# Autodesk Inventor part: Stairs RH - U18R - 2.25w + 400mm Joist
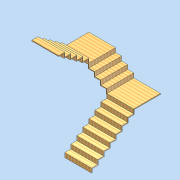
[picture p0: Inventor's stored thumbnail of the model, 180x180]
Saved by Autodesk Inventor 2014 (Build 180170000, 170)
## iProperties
Created: 2012-06
Part Number: Stairs RH - U18R - 2.25w + 400mm Joist
Document SubType Name: Modeling
Designer: david.appleford
Mass: 308572 g
Surface Area: 205460 cm^2
Volume: 308572 cm^3
Density: 1 g/cm^3
Cost Center: £1500.00
Description: Stairs RH - U18R - 2.25w + 400mm Joist
Material: Generic
Appearance: Wood (Pine)
Justset: False
Author: david.appleford
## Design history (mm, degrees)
sketch "Sketch1"
  geometry: L1 (0, 0)-(2970, 0); L2 (2970, 0)-(2970, 2360); L3 (2970, 2360)-(0, 2360); L4 (0, 2360)-(0, 0)
  constraints: 8 end point, 2 parallel, 1 horizontal, 1 perpendicular
  dimensions: "d0" = 2360 distance between parallel lines of L1 L3; "d1" = 2970 distance between parallel lines of L2 L4
extrude "Extrusion1" new body sketch "Sketch1" distance "d2" = 3213; taper "d3" = 0 deg
sketch "Sketch2" dims "d10" = 10, "d20" = 10
  geometry: L1 (178.5, 2836.001)-(178.5, -760.499); L2 (0, 2360)-(0, 0) reference; L3 (3213, 0)-(3213, 2360) reference; L4 (0, 2360)-(3213, 2360) reference; L5 (0, 2360)-(0, 0) reference; L6 (0, 0)-(3213, 0) reference; L7 (357, 2836.001)-(357, -760.499); L8 (535.5, 2836.001)-(535.5, -760.499); L9 (714, 2836.001)-(714, -760.499); L10 (892.5, 2836.001)-(892.5, -760.499); L11 (1071, 2836.001)-(1071, -760.499); L12 (1249.5, 2836.001)-(1249.5, -760.499); L13 (1428, 2836.001)-(1428, -760.499); L14 (1606.5, 2836.001)-(1606.5, -760.499); L15 (1785, 2836.001)-(1785, -760.499); L16 (1963.5, 2836.001)-(1963.5, -760.499); L17 (2142, 2836.001)-(2142, -760.499); L18 (3091.129, 1250)-(-280.443, 1250); L19 (3091.129, 1000)-(-280.443, 1000); L20 (3091.129, 750)-(-280.443, 750); L21 (3091.129, 500)-(-280.443, 500); L22 (3091.129, 250)-(-280.443, 250); L23 (3213, 2360)-(3213, 0); L24 (3213, 0)-(3034.5, 0); L25 (2320.5, 2836.001)-(2320.5, -760.499); L26 (2499, 2836.001)-(2499, -760.499); L27 (2677.5, 2836.001)-(2677.5, -760.499); L28 (2856, 2836.001)-(2856, -760.499); L29 (3034.5, 2836.001)-(3034.5, -760.499); L30 (3034.5, 0)-(3034.5, 250); L31 (3034.5, 250)-(2856, 250); L32 (2856, 250)-(2856, 500); L33 (2856, 500)-(2677.5, 500); L34 (2677.5, 500)-(2677.5, 750); L35 (2677.5, 750)-(2499, 750); L36 (2499, 750)-(2499, 1000); L37 (2499, 1000)-(2320.5, 1000); L38 (2320.5, 1000)-(2320.5, 1250); L39 (2320.5, 1250)-(2142, 1250); L40 (2142, 1250)-(2142, 2360); L41 (2142, 2360)-(3213, 2360); L42 (1428, 2360)-(1428, 1250); L43 (1428, 1250)-(1249.5, 1250); L44 (1249.5, 1250)-(1249.5, 1000); L45 (1249.5, 1000)-(1071, 1000); L46 (1071, 1000)-(1071, 750); L47 (1071, 750)-(892.5, 750); L48 (892.5, 750)-(892.5, 500); L49 (892.5, 500)-(714, 500); L50 (714, 500)-(714, 250); L51 (714, 250)-(535.5, 250); L52 (535.5, 250)-(535.5, 0); L53 (535.5, 0)-(0, 0); 7 further points
  constraints: 96 end point, 51 point on line, 3 perpendicular, 2 vertical, 1 collinear, 1 horizontal, 68 other
  dimensions: "d4" = 178.5 distance between parallel lines of L2 L1 (= d7); "d7" = 178.5 distance of L1.start L7.start; "d14" = 1250 distance between parallel lines of L6 L18; "d17" = 250 distance of L18.start L19.start; "d22" = 1110 distance between parallel lines of L18 L4 (derived); "d77" = 1071 distance between parallel lines of L23 L17 (derived); "d90" = 3213 distance between parallel lines of L2 L3 (derived)
extrude "Extrusion2" cut sketch "Sketch2" stored distance "d23" = 2860; taper "d24" = 0 deg
sketch "Sketch3" dims "d38" = 10, "d39" = 10
  geometry: L1 (178.5, 2836.001)-(178.5, -760.499); L2 (0, 2360)-(0, 0); L3 (0, 2360)-(2828.1, 2360); L4 (0, 2360)-(0, 0); L5 (0, 0)-(2860, 0); L6 (357, 2836.001)-(357, -760.499); L7 (535.5, 2836.001)-(535.5, -760.499); L8 (714, 2836.001)-(714, -760.499); L9 (892.5, 2836.001)-(892.5, -760.499); L10 (1071, 2836.001)-(1071, -760.499); L11 (1249.5, 2836.001)-(1249.5, -760.499); L12 (1428, 2836.001)-(1428, -760.499); L13 (1606.5, 2836.001)-(1606.5, -760.499); L14 (1785, 2836.001)-(1785, -760.499); L15 (1963.5, 2836.001)-(1963.5, -760.499); L16 (2142, 2836.001)-(2142, -760.499); L17 (3070.829, 1250)-(-280.443, 1250); L18 (3070.829, 1000)-(-280.443, 1000); L19 (3070.829, 750)-(-280.443, 750); L20 (3070.829, 500)-(-280.443, 500); L21 (3070.829, 250)-(-280.443, 250); L22 (2677.5, 0)-(535.5, 0); L23 (0, 2360)-(0, 0) reference; L24 (3034.5, 0)-(3034.5, 250) reference; L25 (2320.5, 2836.001)-(2320.5, -760.499); L26 (2499, 2836.001)-(2499, -760.499); L27 (2677.5, 2836.001)-(2677.5, -760.499); L28 (2856, 2836.001)-(2856, -760.499); L29 (3034.5, 2836.001)-(3034.5, -760.499); L30 (2677.5, 0)-(2677.5, 250); L31 (2677.5, 250)-(2499, 250); L32 (2499, 250)-(2499, 500); L33 (2499, 500)-(2320.5, 500); L34 (2320.5, 500)-(2320.5, 750); L35 (2320.5, 750)-(2142, 750); L36 (2142, 750)-(2142, 1000); L37 (2142, 1000)-(1963.5, 1000); L38 (1963.5, 1000)-(1963.5, 1250); L39 (1963.5, 1250)-(1785, 1250); L40 (1785, 1250)-(1785, 2360); L41 (1785, 2360)-(1428, 2360); L42 (1428, 2360)-(1428, 1250); L43 (1428, 1250)-(1249.5, 1250); L44 (1249.5, 1250)-(1249.5, 1000); L45 (1249.5, 1000)-(1071, 1000); L46 (1071, 1000)-(1071, 750); L47 (1071, 750)-(892.5, 750); L48 (892.5, 750)-(892.5, 500); L49 (892.5, 500)-(714, 500); L50 (714, 500)-(714, 250); L51 (714, 250)-(535.5, 250); L52 (535.5, 250)-(535.5, 0); 9 further points
  constraints: 100 end point, 57 point on line, 2 collinear, 2 vertical, 1 horizontal, 1 perpendicular, 68 other
  dimensions: "d33" = 178.5 distance between parallel lines of L2 L1 (= d34); "d34" = 178.5 distance of L1.start L6.start; "d35" = 1250 distance between parallel lines of L5 L17; "d36" = 250 distance of L17.start L18.start; "d37" = 1110 distance between parallel lines of L17 L3 (derived); "d91" = 3034.5 distance between parallel lines of L2 L24 (derived)
extrude "Extrusion3" cut sketch "Sketch3" distance "d40" = 1110; taper "d41" = 0 deg
sketch "Sketch4"
  geometry: L1 (0, 2360)-(0, 1250); L2 (1860, 1250)-(1110, 1250); L3 (1110, 1250)-(1110, 0); L4 (1110, 0)-(1860, 0); L5 (1860, 0)-(1860, 1250); L6 (2970, 250)-(2970, 0) reference; L7 (2970, 2360)-(2970, 1250) reference; L8 (0, 2360)-(2970, 2360) reference; L9 (0, 1250)-(0, 2360) reference; L10 (0, 1250)-(2970, 1250) reference
  constraints: 10 end point, 2 parallel, 1 horizontal, 1 perpendicular
  dimensions: "d92" = 1110 distance between parallel lines of L6 L5 (= d94); "d93" = 750 distance between parallel lines of L3 L5; "d94" = 1110 distance between parallel lines of L10 L8 (derived)
extrude "Extrusion4" cut sketch "Sketch4" stored distance "d45" = 1180; taper "d46" = 0 deg
sketch "Sketch5"
  geometry: L1 (1249.5, 1250)-(1428, 1250) reference; L2 (1785, 2360)-(2142, 2360) reference; L3 (0, 2360)-(0, 0) reference; L4 (0, 0)-(535.5, 0) reference; L5 (1394, 1275)-(1215.5, 1275); L6 (1215.5, 1275)-(1215.5, 1025); L7 (1215.5, 1025)-(1037, 1025); L8 (1037, 1025)-(1037, 775); L9 (1037, 775)-(858.5, 775); L10 (858.5, 775)-(858.5, 525); L11 (858.5, 525)-(680, 525); L12 (680, 525)-(680, 275); L13 (680, 275)-(501.5, 275); L14 (501.5, 275)-(501.5, 25); L15 (501.5, 25)-(0, 25); L16 (1394, 2360)-(0, 2360); L17 (0, 2360)-(0, 25); L18 (1428, 1250)-(1428, 2360) reference; L19 (535.5, 0)-(535.5, 250) reference; L20 (535.5, 250)-(714, 250) reference; L21 (714, 250)-(714, 500) reference; L22 (714, 500)-(892.5, 500) reference; L23 (892.5, 500)-(892.5, 750) reference; L24 (892.5, 750)-(1071, 750) reference; L25 (1071, 750)-(1071, 1000) reference; L26 (1071, 1000)-(1249.5, 1000) reference; L27 (1249.5, 1000)-(1249.5, 1250) reference; L28 (1785, 2360)-(1785, 1250) reference; L29 (1785, 1250)-(1963.5, 1250) reference; L30 (1963.5, 1250)-(1963.5, 1000) reference; L31 (1963.5, 1000)-(2142, 1000) reference; L32 (2142, 1000)-(2142, 750) reference; L33 (2142, 750)-(2320.5, 750) reference; L34 (2320.5, 750)-(2320.5, 500) reference; L35 (2320.5, 500)-(2499, 500) reference; L36 (2499, 500)-(2499, 250) reference; L37 (2499, 250)-(2677.5, 250) reference; L38 (2677.5, 250)-(2677.5, 0) reference; L39 (2677.5, 0)-(3034.5, 0) reference; L40 (3034.5, 0)-(3034.5, 250) reference; L41 (3034.5, 250)-(2856, 250) reference; L42 (2856, 250)-(2856, 500) reference; L43 (2856, 500)-(2677.5, 500) reference; L44 (2677.5, 500)-(2677.5, 750) reference; L45 (2677.5, 750)-(2499, 750) reference; L46 (2499, 750)-(2499, 1000) reference; L47 (2499, 1000)-(2320.5, 1000) reference; L48 (2320.5, 1000)-(2320.5, 1250) reference; L49 (2320.5, 1250)-(2142, 1250) reference; L50 (2142, 1250)-(2142, 2360) reference; L51 (1394, 1275)-(1394, 2360); L52 (0, 2360)-(1428, 2360) reference; 1 further point
  constraints: 28 end point, 4 parallel, 3 perpendicular, 1 collinear, 1 point on line
  dimensions: "d48" = 25 distance between parallel lines of L1 L5; "d53" = 25 distance between parallel lines of L4 L15 (= d48); "d95" = 178.5 distance between parallel lines of L8 L6; "d96" = 178.5 distance between parallel lines of L10 L8 (= d95); "d97" = 178.5 distance between parallel lines of L12 L10 (= d96); "d98" = 178.5 distance between parallel lines of L14 L12; "d99" = 34 distance between parallel lines of L6 L27; "d100" = 178.5 distance between parallel lines of L51 L6 (= d95)
extrude "Extrusion5" cut sketch "Sketch5" stored distance "d59" = 1180; taper "d60" = 0 deg
sketch "Sketch9"
  geometry: L1 (-357, 1110)-(-357, 0) reference; L2 (-357, 0)-(-178.5, 0) reference; L3 (-178.5, 0)-(-178.5, -250) reference; L4 (-178.5, -250)-(0, -250) reference; L5 (0, -250)-(0, -500) reference; L6 (0, -500)-(178.5, -500) reference; L7 (178.5, -500)-(178.5, -750) reference; L8 (178.5, -750)-(357, -750) reference; L9 (357, -750)-(357, -1000) reference; L10 (357, -1000)-(535.5, -1000) reference; L11 (535.5, -1000)-(535.5, -1250) reference; L12 (535.5, -1250)-(892.5, -1250) reference; L13 (892.5, -1250)-(892.5, -1000) reference; L14 (892.5, -1000)-(714, -1000) reference; L15 (714, -1000)-(714, -750) reference; L16 (714, -750)-(535.5, -750) reference; L17 (535.5, -750)-(535.5, -500) reference; L18 (535.5, -500)-(357, -500) reference; L19 (357, -500)-(357, -250) reference; L20 (357, -250)-(178.5, -250) reference; L21 (178.5, -250)-(178.5, 0) reference; L22 (178.5, 0)-(0, 0) reference; L23 (0, 0)-(0, 1110) reference; L24 (-357, 1110)-(0, 1110) reference; 1 further point
extrude "Extrusion9" cut sketch "Sketch9" stored distance "d101" = 10; taper "d102" = 0 deg
sketch "Sketch10"
  geometry: L1 (0, 714)-(0, 0) reference; L2 (0, 0)-(1860, 0) reference; L3 (1860, 748)-(1860, 0) reference; L4 (1860, 748)-(-1110, 748) reference; L5 (-1110, 748)-(-1110, 714) reference; L6 (-1110, 714)-(0, 714) reference; L7 (750, 0)-(750, -178.5) reference; L8 (750, -178.5)-(1860, -178.5) reference; L9 (1860, 0)-(1860, -178.5) reference; L10 (750, 0)-(1860, 0) reference; L11 (750, 0)-(750, 178.5); L12 (750, 178.5)-(500, 178.5); L13 (500, 178.5)-(500, 357); L14 (500, 357)-(250, 357); L15 (250, 357)-(250, 535.5); L16 (250, 535.5)-(0, 535.5); L17 (0, 535.5)-(0, 0); L18 (750, 0)-(0, 0); 1 further point
  constraints: 16 end point, 1 point on line
  dimensions: "d103" = 250 distance between parallel lines of L13 L11; "d104" = 250 distance between parallel lines of L15 L13 (= d103); "d105" = 250 distance between parallel lines of L17 L15 (= d103); "d106" = 178.5 distance between parallel lines of L12 L18; "d107" = 178.5 distance between parallel lines of L14 L12 (= d106); "d108" = 178.5 distance between parallel lines of L16 L14 (= d106); "d109" = 178.5 distance between parallel lines of L6 L16 (derived)
extrude "Extrusion10" cut sketch "Sketch10" stored distance "d110" = 10; taper "d111" = 0 deg
sketch "Sketch11"
  geometry: L1 (1860, -535.5)-(1860, -714) reference; L2 (1860, -714)-(2970, -714) reference; L3 (2970, 34)-(2970, -714) reference; L4 (2970, 34)-(0, 34) reference; L5 (0, 34)-(0, 0) reference; L6 (0, 0)-(1110, 0) reference; L7 (1110, 0)-(1110, -178.5) reference; L8 (1110, -178.5)-(1360, -178.5) reference; L9 (1360, -178.5)-(1360, -357) reference; L10 (1360, -357)-(1610, -357) reference; L11 (1610, -357)-(1610, -535.5) reference; L12 (1610, -535.5)-(1860, -535.5) reference; L13 (1885, -680)-(1885, -501.5); L14 (1885, -501.5)-(1635, -501.5); L15 (1635, -501.5)-(1635, -323); L16 (1635, -323)-(1385, -323); L17 (1385, -323)-(1385, -144.5); L18 (1385, -144.5)-(1135, -144.5); L19 (1135, -144.5)-(1135, 34); L20 (2970, -680)-(2970, 34); L21 (2970, 34)-(1860, 34); L22 (2970, -680)-(1885, -680); L23 (2970, 212.5)-(2970, 34) reference; L24 (0, 212.5)-(2970, 212.5) reference; L25 (0, 34)-(0, 212.5) reference; L26 (0, 34)-(2970, 34) reference; L27 (1860, 212.5)-(1860, 391) reference; L28 (1860, 212.5)-(2970, 212.5) reference; L29 (2970, 391)-(2970, 212.5) reference; L30 (1860, 391)-(2970, 391) reference; L31 (1110, 391)-(1110, 212.5) reference; L32 (0, 391)-(1110, 391) reference; L33 (0, 212.5)-(0, 391) reference; L34 (0, 212.5)-(1110, 212.5) reference; L35 (1860, 212.5)-(1110, 212.5); L36 (1110, 212.5)-(1110, 34); L37 (1110, 34)-(1135, 34); L38 (1860, 34)-(1860, 212.5); 1 further point
  constraints: 28 end point, 2 point on line
  dimensions: "d112" = 25 distance between parallel lines of L1 L13; "d113" = 25 distance between parallel lines of L11 L15 (= d112); "d114" = 25 distance between parallel lines of L9 L17 (= d112); "d115" = 25 distance between parallel lines of L7 L19 (= d112); "d116" = 34 distance between parallel lines of L14 L12; "d117" = 34 distance between parallel lines of L16 L10 (= d116); "d118" = 34 distance between parallel lines of L18 L8 (= d116); "d119" = 34 distance between parallel lines of L22 L2
extrude "Extrusion11" cut sketch "Sketch11" stored distance "d120" = 10; taper "d121" = 0 deg
sketch "Sketch12"
  geometry: L1 (34, 0)-(34, 1110) reference; L2 (34, 1110)-(0, 1110) reference; L3 (0, 1110)-(0, 0) reference; L4 (0, 0)-(-178.5, 0) reference; L5 (-178.5, 0)-(-178.5, -250) reference; L6 (-178.5, -250)-(-357, -250) reference; L7 (-357, -250)-(-357, -500) reference; L8 (-357, -500)-(-535.5, -500) reference; L9 (-535.5, -500)-(-535.5, -750) reference; L10 (-535.5, -750)-(-714, -750) reference; L11 (-714, -750)-(-714, -1000) reference; L12 (-714, -1000)-(-892.5, -1000) reference; L13 (-892.5, -1000)-(-892.5, -1250) reference; L14 (2142, -1250)-(-892.5, -1250) reference; L15 (2142, -1250)-(2142, -1225) reference; L16 (2142, -1225)-(1640.5, -1225) reference; L17 (1640.5, -1225)-(1640.5, -975) reference; L18 (1640.5, -975)-(1462, -975) reference; L19 (1462, -975)-(1462, -725) reference; L20 (1462, -725)-(1283.5, -725) reference; L21 (1283.5, -725)-(1283.5, -475) reference; L22 (1283.5, -475)-(1105, -475) reference; L23 (1105, -475)-(1105, -225) reference; L24 (1105, -225)-(926.5, -225) reference; L25 (926.5, -225)-(926.5, 25) reference; L26 (926.5, 25)-(748, 25) reference; L27 (748, 25)-(748, 0) reference; L28 (748, 0)-(34, 0) reference; L29 (-858.5, -1250)-(-858.5, -1025); L30 (-858.5, -1025)-(-680, -1025); L31 (-680, -1025)-(-680, -775); L32 (-680, -775)-(-501.5, -775); L33 (-501.5, -775)-(-501.5, -525); L34 (-501.5, -525)-(-323, -525); L35 (-323, -525)-(-323, -275); L36 (-323, -275)-(-144.5, -275); L37 (-144.5, -275)-(-144.5, -25); L38 (-144.5, -25)-(34, -25); L39 (34, -25)-(34, 0); L40 (34, 0)-(748, 0); L41 (748, 0)-(748, 25); L42 (748, 25)-(926.5, 25); L43 (926.5, 25)-(926.5, -225); L44 (926.5, -225)-(1105, -225); L45 (1105, -225)-(1105, -475); L46 (1105, -475)-(1283.5, -475); L47 (1283.5, -475)-(1283.5, -725); L48 (1283.5, -725)-(1462, -725); L49 (1462, -725)-(1462, -975); L50 (1462, -975)-(1640.5, -975); L51 (1640.5, -975)-(1640.5, -1225); L52 (1640.5, -1225)-(2142, -1225); L53 (2142, -1225)-(2142, -1250); L54 (2142, -1250)-(-858.5, -1250); 1 further point
  constraints: 52 end point, 1 point on line
  dimensions: "d122" = 34 distance between parallel lines of L29 L13; "d123" = 25 distance between parallel lines of L12 L30; "d124" = 34 distance between parallel lines of L31 L11 (= d122); "d125" = 25 distance between parallel lines of L10 L32 (= d123); "d126" = 25 distance between parallel lines of L8 L34 (= d123); "d127" = 34 distance between parallel lines of L33 L9 (= d122); "d128" = 34 distance between parallel lines of L35 L7 (= d122); "d129" = 34 distance between parallel lines of L37 L5 (= d122); "d130" = 25 distance between parallel lines of L6 L36 (= d123); "d131" = 25 distance between parallel lines of L4 L38 (= d123)
extrude "Extrusion12" cut sketch "Sketch12" stored distance "d132" = 10; taper "d133" = 0 deg
mirror "Mirror1"
sketch "Sketch13"
  geometry: L1 (926.5, -1225)-(1428, -1225) reference; L2 (926.5, -975)-(926.5, -1225) reference; L3 (748, -975)-(926.5, -975) reference; L4 (748, -725)-(748, -975) reference; L5 (569.5, -725)-(748, -725) reference; L6 (569.5, -475)-(569.5, -725) reference; L7 (391, -475)-(569.5, -475) reference; L8 (391, -225)-(391, -475) reference; L9 (212.5, -225)-(391, -225) reference; L10 (212.5, 25)-(212.5, -225) reference; L11 (34, 25)-(212.5, 25) reference; L12 (34, 1110)-(34, 25) reference; L13 (34, 1110)-(0, 1110) reference; L14 (0, 0)-(0, 1110) reference; L15 (178.5, 0)-(0, 0) reference; L16 (178.5, -250)-(178.5, 0) reference; L17 (357, -250)-(178.5, -250) reference; L18 (357, -500)-(357, -250) reference; L19 (535.5, -500)-(357, -500) reference; L20 (535.5, -750)-(535.5, -500) reference; L21 (714, -750)-(535.5, -750) reference; L22 (714, -1000)-(714, -750) reference; L23 (892.5, -1000)-(714, -1000) reference; L24 (892.5, -1250)-(892.5, -1000) reference; L25 (1428, -1250)-(892.5, -1250) reference; L26 (1428, -1225)-(1428, -1250) reference; L27 (1071, -1250)-(1105, -1250); L28 (1105, -1250)-(1105, -1500); L29 (1105, -1500)-(1071, -1500); L30 (1071, -1500)-(1071, -1250); L31 (1105, -1500)-(1249.5, -1500); L32 (1249.5, -1500)-(1249.5, -1475); L33 (1249.5, -1475)-(1105, -1475); L34 (1105, -1475)-(1105, -1500); L35 (1249.5, -1475)-(1283.5, -1475); L36 (1283.5, -1475)-(1283.5, -1750); L37 (1283.5, -1750)-(1249.5, -1750); L38 (1249.5, -1750)-(1249.5, -1475); L39 (1283.5, -1750)-(1428, -1750); L40 (1428, -1750)-(1428, -1725); L41 (1428, -1725)-(1283.5, -1725); L42 (1283.5, -1725)-(1283.5, -1750); L43 (1428, -1225)-(1428, -1250) reference
  constraints: 32 end point, 8 parallel, 4 horizontal, 4 perpendicular, 1 collinear, 1 point on line
  dimensions: "d134" = 34 distance between parallel lines of L28 L30; "d135" = 34 distance between parallel lines of L36 L38 (= d134); "d136" = 25 distance between parallel lines of L33 L31; "d137" = 25 distance between parallel lines of L41 L39 (= d136); "d138" = 178.5 distance between parallel lines of L40 L38; "d139" = 250 distance between parallel lines of L31 L39; "d140" = 250 distance between parallel lines of L25 L29 (= d139); "d141" = 178.5 distance between parallel lines of L30 L38 (= d138); "d142" = 178.5 distance between parallel lines of L30 L24 (derived)
extrude "Extrusion13" join sketch "Sketch13" stored distance "d143" = 10; taper "d144" = 0 deg
sketch "Sketch14"
  geometry: L1 (926.5, -1225)-(1428, -1225) reference; L2 (926.5, -975)-(926.5, -1225) reference; L3 (748, -975)-(926.5, -975) reference; L4 (748, -725)-(748, -975) reference; L5 (569.5, -725)-(748, -725) reference; L6 (569.5, -475)-(569.5, -725) reference; L7 (391, -475)-(569.5, -475) reference; L8 (391, -225)-(391, -475) reference; L9 (212.5, -225)-(391, -225) reference; L10 (212.5, 25)-(212.5, -225) reference; L11 (34, 25)-(212.5, 25) reference; L12 (34, 1110)-(34, 25) reference; L13 (34, 1110)-(0, 1110) reference; L14 (0, 0)-(0, 1110) reference; L15 (178.5, 0)-(0, 0) reference; L16 (178.5, -250)-(178.5, 0) reference; L17 (357, -250)-(178.5, -250) reference; L18 (357, -500)-(357, -250) reference; L19 (535.5, -500)-(357, -500) reference; L20 (535.5, -750)-(535.5, -500) reference; L21 (714, -750)-(535.5, -750) reference; L22 (714, -1000)-(714, -750) reference; L23 (892.5, -1000)-(714, -1000) reference; L24 (892.5, -1250)-(892.5, -1000) reference; L25 (1071, -1250)-(892.5, -1250) reference; L26 (1071, -1250)-(1071, -1500) reference; L27 (1071, -1500)-(1249.5, -1500) reference; L28 (1249.5, -1500)-(1249.5, -1750) reference; L29 (1249.5, -1750)-(1428, -1750) reference; L30 (1428, -1750)-(1428, -1725) reference; L31 (1428, -1725)-(1283.5, -1725) reference; L32 (1283.5, -1725)-(1283.5, -1475) reference; L33 (1283.5, -1475)-(1105, -1475) reference; L34 (1105, -1475)-(1105, -1250) reference; L35 (1428, -1250)-(1105, -1250) reference; L36 (1428, -1225)-(1428, -1250) reference; L37 (1105, -1250)-(1428, -1250); L38 (1428, -1250)-(1428, -1225); L39 (1428, -1225)-(1105, -1225); L40 (1105, -1225)-(1105, -1250); 1 further point
  constraints: 8 end point, 2 parallel, 1 horizontal, 1 perpendicular
extrude "Extrusion14" cut sketch "Sketch14" stored distance "d145" = 10; taper "d146" = 0 deg
body "Solid1"
node "Projected Loop1"
node "Projected Loop4"
node "Projected Loop6"
node "Projected Loop7"
node "Projected Loop8"
node "Projected Loop9"
node "Projected Loop10"
node "Projected Loop11"
node "Projected Loop12"
node "Projected Loop13"
node "Projected Loop14"
node "Projected Loop15"
node "Projected Loop16"
